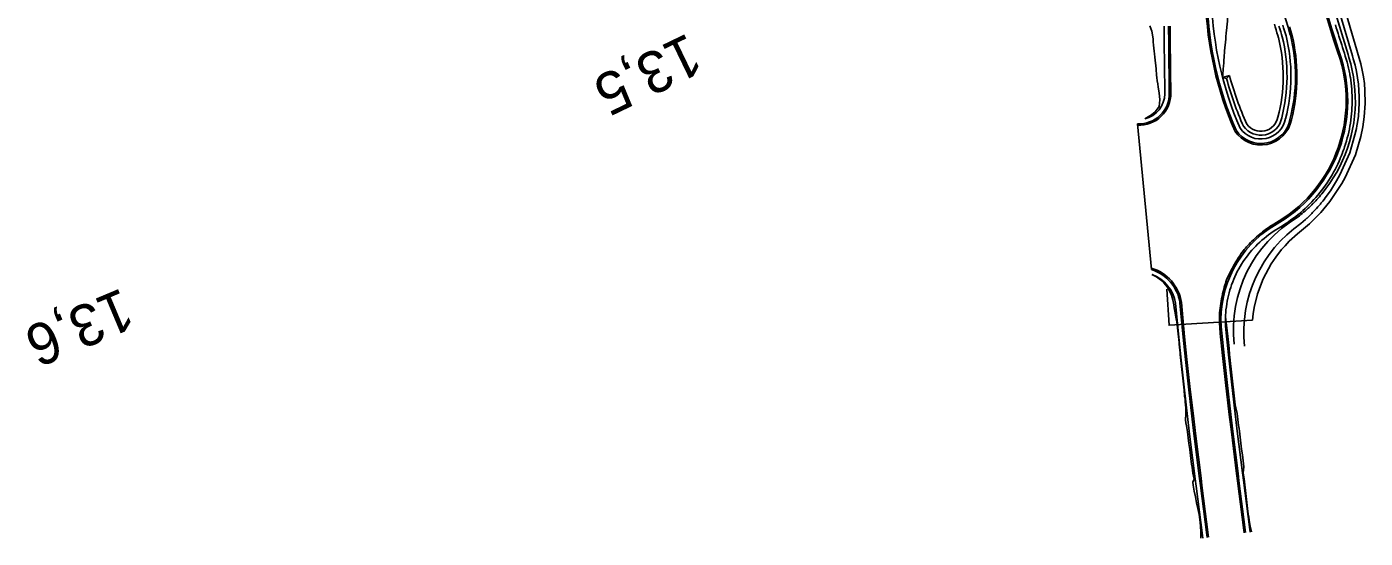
# Model space of a CAD drawing. Extents: x -723225 to -722352, y -1040354 to -1039760.
# Drawn here: x -722813.7 to -722589.4, y -1040267.5 to -1040181.7 of the extents above; entities that cross this region are included whole.
import ezdxf

# ---------------------------------------------------------------- set-up
doc = ezdxf.new("R2010")
doc.units = 0
for name, color, linetype in [('SO 03_01_01', 7, 'Continuous'), ('SO 05_30_01', 7, 'Continuous'), ('SO 05_30_02', 7, 'Continuous'), ('SO 05_73_06', 7, 'Continuous')]:
    doc.layers.add(name, color=color, linetype=linetype)

msp = doc.modelspace()

# ---------------------------------------------------------------- linework, layer by layer
at = {"layer": 'SO 05_30_01'}
msp.add_line((-722625.21, -1040222.47), (-722627.56, -1040198.01), dxfattribs=at)
for points in [[(-722613.29, -1040190.21), (-722613.26, -1040189.78), (-722613.19, -1040188.77), (-722613.16, -1040188.36), (-722613.11, -1040187.77), (-722613.08, -1040187.36), (-722613.03, -1040186.78), (-722612.95, -1040185.86), (-722612.95, -1040185.78), (-722612.86, -1040184.78), (-722612.83, -1040184.36), (-722612.77, -1040183.77), (-722612.73, -1040183.36), (-722612.68, -1040182.78), (-722612.6, -1040181.86), (-722612.59, -1040181.77), (-722612.49, -1040180.77), (-722612.45, -1040180.36), (-722612.38, -1040179.89), (-722612.29, -1040179.56), (-722612.17, -1040179.07), (-722612.02, -1040178.37)], [(-722626.35, -1040197.16), (-722625.2, -1040196.52), (-722624.58, -1040196.01), (-722623.94, -1040195.12), (-722623.82, -1040193.96), (-722623.9, -1040192.82), (-722624.07, -1040191.85), (-722624.16, -1040191.3), (-722624.26, -1040190.82), (-722624.32, -1040190.24), (-722624.36, -1040189.82), (-722624.45, -1040188.82), (-722624.51, -1040188.24), (-722624.55, -1040187.82), (-722624.65, -1040186.82), (-722624.7, -1040186.24), (-722624.75, -1040185.82), (-722624.85, -1040184.82), (-722624.91, -1040184.24), (-722624.95, -1040183.82), (-722625, -1040183.39), (-722625.18, -1040182.49), (-722625.33, -1040182.03), (-722625.5, -1040181.58)], [(-722622.97, -1040192.95), (-722622.97, -1040192.79), (-722622.98, -1040192.47), (-722622.98, -1040192.15), (-722622.98, -1040191.83), (-722622.99, -1040191.51), (-722622.99, -1040191.19), (-722623, -1040190.87), (-722623, -1040190.55), (-722623.01, -1040190.24), (-722623.01, -1040189.92), (-722623.02, -1040189.6), (-722623.02, -1040189.28), (-722623.02, -1040188.96), (-722623.02, -1040188.94), (-722623.03, -1040188.64), (-722623.03, -1040188.32), (-722623.03, -1040188), (-722623.04, -1040187.68), (-722623.04, -1040187.37), (-722623.04, -1040187.35), (-722623.05, -1040187.05), (-722623.05, -1040186.73), (-722623.05, -1040186.41), (-722623.06, -1040186.09), (-722623.06, -1040185.77), (-722623.06, -1040185.46), (-722623.07, -1040185.14), (-722623.07, -1040184.82), (-722623.07, -1040184.5), (-722623.07, -1040184.18), (-722623.08, -1040183.86), (-722623.08, -1040183.55), (-722623.08, -1040183.23), (-722623.09, -1040182.91), (-722623.09, -1040182.59), (-722623.09, -1040182.27), (-722623.09, -1040181.95), (-722623.1, -1040181.64)], [(-722622.22, -1040192.84), (-722622.22, -1040192.78), (-722622.23, -1040192.46), (-722622.23, -1040192.14), (-722622.23, -1040191.82), (-722622.24, -1040191.5), (-722622.24, -1040191.18), (-722622.25, -1040190.86), (-722622.25, -1040190.54), (-722622.26, -1040190.23), (-722622.26, -1040189.91), (-722622.27, -1040189.59), (-722622.27, -1040189.27), (-722622.27, -1040188.95), (-722622.27, -1040188.93), (-722622.28, -1040188.63), (-722622.28, -1040188.31), (-722622.29, -1040187.99), (-722622.29, -1040187.68), (-722622.29, -1040187.36), (-722622.29, -1040187.34), (-722622.3, -1040187.04), (-722622.3, -1040186.72), (-722622.3, -1040186.4), (-722622.31, -1040186.08), (-722622.31, -1040185.77), (-722622.31, -1040185.45), (-722622.32, -1040185.13), (-722622.32, -1040184.81), (-722622.32, -1040184.49), (-722622.32, -1040184.17), (-722622.33, -1040183.86), (-722622.33, -1040183.54), (-722622.33, -1040183.22), (-722622.34, -1040182.9), (-722622.34, -1040182.58), (-722622.34, -1040182.27), (-722622.34, -1040181.95), (-722622.35, -1040181.63)], [(-722621.97, -1040192.84), (-722621.97, -1040192.77), (-722621.98, -1040192.45), (-722621.98, -1040192.13), (-722621.98, -1040191.82), (-722621.99, -1040191.5), (-722621.99, -1040191.18), (-722622, -1040190.86), (-722622, -1040190.54), (-722622.01, -1040190.22), (-722622.01, -1040189.9), (-722622.02, -1040189.58), (-722622.02, -1040189.27), (-722622.02, -1040188.95), (-722622.02, -1040188.92), (-722622.03, -1040188.63), (-722622.03, -1040188.31), (-722622.04, -1040187.99), (-722622.04, -1040187.67), (-722622.04, -1040187.36), (-722622.04, -1040187.34), (-722622.05, -1040187.04), (-722622.05, -1040186.72), (-722622.05, -1040186.4), (-722622.06, -1040186.08), (-722622.06, -1040185.76), (-722622.06, -1040185.45), (-722622.07, -1040185.13), (-722622.07, -1040184.81), (-722622.07, -1040184.49), (-722622.07, -1040184.17), (-722622.08, -1040183.85), (-722622.08, -1040183.54), (-722622.08, -1040183.22), (-722622.09, -1040182.9), (-722622.09, -1040182.58), (-722622.09, -1040182.26), (-722622.09, -1040181.95), (-722622.1, -1040181.63)], [(-722616.94, -1040267.53), (-722616.95, -1040266.52), (-722616.97, -1040265.52), (-722617.1, -1040264.39), (-722617.23, -1040263.53), (-722617.44, -1040262.55), (-722617.65, -1040261.57), (-722617.65, -1040261.57), (-722617.86, -1040260.59), (-722618.06, -1040259.61), (-722618.2, -1040258.61), (-722618.27, -1040258.12), (-722618.03, -1040257.59), (-722618.28, -1040256.61), (-722618.42, -1040255.62), (-722618.49, -1040255.12), (-722618.56, -1040254.63), (-722618.69, -1040253.64), (-722618.81, -1040252.64), (-722618.81, -1040252.64), (-722618.94, -1040251.65), (-722619.06, -1040250.66), (-722619.12, -1040250.16), (-722619.18, -1040249.67), (-722619.36, -1040248.68), (-722619.47, -1040248.18), (-722619.52, -1040247.69), (-722619.48, -1040246.68), (-722619.45, -1040246.17), (-722619.43, -1040245.67), (-722619.54, -1040244.67), (-722619.59, -1040244.17), (-722619.65, -1040243.68), (-722619.75, -1040242.68), (-722619.81, -1040242.18), (-722619.86, -1040241.69), (-722619.97, -1040240.7), (-722620.02, -1040240.19), (-722620.07, -1040239.7), (-722620.18, -1040238.71), (-722620.18, -1040238.69), (-722620.28, -1040237.71), (-722620.33, -1040237.2), (-722620.38, -1040236.72), (-722620.48, -1040235.72), (-722620.49, -1040235.7), (-722620.58, -1040234.73), (-722620.64, -1040234.21), (-722620.68, -1040233.73), (-722620.78, -1040232.74), (-722620.78, -1040232.71), (-722620.88, -1040231.74), (-722620.98, -1040231.22), (-722621.08, -1040230.75), (-722621.23, -1040229.76), (-722621.24, -1040229.74), (-722621.4, -1040228.85), (-722621.47, -1040228.35)], [(-722616.62, -1040267.5), (-722616.68, -1040267.07), (-722617.74, -1040258.8), (-722617.89, -1040257.57), (-722618.77, -1040250.51), (-722619.12, -1040247.62), (-722619.75, -1040242.2), (-722620.25, -1040237.63), (-722620.64, -1040233.86), (-722621.19, -1040228.1)], [(-722615.88, -1040267.4), (-722615.94, -1040266.97), (-722617, -1040258.7), (-722617.15, -1040257.48), (-722618.03, -1040250.42), (-722618.38, -1040247.53), (-722619, -1040242.11), (-722619.5, -1040237.55), (-722619.89, -1040233.79), (-722620.44, -1040228.01)], [(-722615.63, -1040267.37), (-722615.69, -1040266.94), (-722616.75, -1040258.67), (-722616.9, -1040257.45), (-722617.78, -1040250.39), (-722618.13, -1040247.5), (-722618.76, -1040242.08), (-722619.26, -1040237.53), (-722619.65, -1040233.76), (-722620.2, -1040227.98)], [(-722609.68, -1040266.61), (-722609.74, -1040266.18), (-722610.8, -1040257.91), (-722610.95, -1040256.69), (-722611.82, -1040249.66), (-722612.17, -1040246.79), (-722612.79, -1040241.41), (-722613.29, -1040236.89), (-722613.68, -1040233.16), (-722613.78, -1040232.1)], [(-722609.43, -1040266.57), (-722609.49, -1040266.14), (-722610.55, -1040257.88), (-722610.7, -1040256.66), (-722611.58, -1040249.63), (-722611.92, -1040246.76), (-722612.54, -1040241.38), (-722613.04, -1040236.86), (-722613.43, -1040233.14), (-722613.53, -1040232.09)], [(-722608.47, -1040266.46), (-722608.65, -1040265.48), (-722608.86, -1040264.5), (-722608.92, -1040264), (-722608.98, -1040263.5), (-722609.1, -1040262.51), (-722609.22, -1040261.52), (-722609.22, -1040261.52), (-722609.34, -1040260.52), (-722609.46, -1040259.53), (-722609.58, -1040258.54), (-722609.7, -1040257.55), (-722609.82, -1040256.55), (-722609.82, -1040256.55), (-722609.75, -1040255.54), (-722609.86, -1040254.54), (-722609.86, -1040254.54), (-722609.98, -1040253.55), (-722610.1, -1040252.56), (-722610.1, -1040252.56), (-722610.23, -1040251.57), (-722610.29, -1040251.07), (-722610.35, -1040250.57), (-722610.47, -1040249.58), (-722610.53, -1040249.09), (-722610.6, -1040248.59), (-722610.72, -1040247.6), (-722610.78, -1040247.11), (-722610.84, -1040246.6), (-722611.08, -1040245.63), (-722611.18, -1040245.14), (-722611.23, -1040244.64), (-722611.35, -1040243.64), (-722611.4, -1040243.16), (-722611.46, -1040242.65), (-722611.57, -1040241.66), (-722611.62, -1040241.17), (-722611.68, -1040240.66), (-722611.78, -1040239.68), (-722611.79, -1040239.67), (-722611.89, -1040238.67), (-722611.95, -1040238.19), (-722612, -1040237.68), (-722612.11, -1040236.7), (-722612.11, -1040236.69), (-722612.21, -1040235.69), (-722612.26, -1040235.21), (-722612.32, -1040234.7), (-722612.42, -1040233.7), (-722612.52, -1040232.73), (-722612.52, -1040232.71), (-722612.8, -1040230.38)], [(-722608.69, -1040266.48), (-722608.74, -1040266.05), (-722609.8, -1040257.79), (-722609.96, -1040256.57), (-722610.83, -1040249.54), (-722611.18, -1040246.67), (-722611.8, -1040241.3), (-722612.3, -1040236.78), (-722612.68, -1040233.06), (-722612.79, -1040231.87)]]:
    msp.add_lwpolyline(points, dxfattribs=at)
for centre, radius, start, end in [((-722627.32, -1040192.92), 5.1, 267.2895, 0.8852), ((-722627.32, -1040192.92), 5.35, 267.6754, 0.8852), ((-722627.32, -1040192.92), 4.35, 282.8795, 359.5116), ((-722627.31, -1040229.1), 7.21, 8.9645, 73.2104), ((-722627.31, -1040229.1), 6.96, 9.0345, 72.357), ((-722627.56, -1040228.91), 6.11, 5.2223, 66.5396), ((-722627.31, -1040229.1), 6.21, 9.244, 69.198)]:
    msp.add_arc(centre, radius, start, end, dxfattribs=at)
at = {"layer": 'SO 05_30_02'}
for p, q in [((-722602.08, -1040181.72), (-722601.69, -1040183)), ((-722612.14, -1040189.89), (-722613.29, -1040190.21)), ((-722613.29, -1040190.21), (-722612.62, -1040190.41)), ((-722612.62, -1040190.41), (-722612.14, -1040189.89))]:
    msp.add_line(p, q, dxfattribs=at)
for points in [[(-722600.81, -1040213.73), (-722600.42, -1040213.43), (-722600.18, -1040213.24), (-722599.94, -1040213.04), (-722599.76, -1040212.88), (-722599.71, -1040212.84), (-722599.47, -1040212.64), (-722599.24, -1040212.44), (-722599.01, -1040212.23), (-722598.93, -1040212.15), (-722598.78, -1040212.02), (-722598.56, -1040211.81), (-722598.34, -1040211.59), (-722598.14, -1040211.39), (-722598.12, -1040211.37), (-722597.91, -1040211.15), (-722597.69, -1040210.93), (-722597.48, -1040210.7), (-722597.38, -1040210.59), (-722597.28, -1040210.47), (-722597.07, -1040210.24), (-722596.87, -1040210), (-722596.67, -1040209.77), (-722596.66, -1040209.75), (-722596.44, -1040209.48), (-722595.98, -1040208.88), (-722595.33, -1040207.99), (-722594.73, -1040207.07), (-722594.17, -1040206.12), (-722593.66, -1040205.14), (-722593.18, -1040204.15), (-722592.75, -1040203.13), (-722592.37, -1040202.09), (-722592.04, -1040201.04), (-722591.75, -1040199.98), (-722591.51, -1040198.9), (-722591.42, -1040198.39), (-722591.32, -1040197.82), (-722591.18, -1040196.72), (-722591.08, -1040195.63), (-722591.04, -1040194.52), (-722591.05, -1040193.42), (-722591.1, -1040192.32), (-722591.21, -1040191.22), (-722591.36, -1040190.13), (-722591.56, -1040189.05), (-722591.81, -1040187.97), (-722592.11, -1040186.91), (-722592.27, -1040186.38), (-722594.33, -1040179.64)], [(-722591.94, -1040202.88), (-722591.11, -1040199.87), (-722590.87, -1040198.82), (-722590.77, -1040198.33), (-722590.68, -1040197.77), (-722590.53, -1040196.7), (-722590.43, -1040195.63), (-722590.38, -1040194.55), (-722590.38, -1040193.48), (-722590.43, -1040192.4), (-722590.52, -1040191.33), (-722590.67, -1040190.27), (-722590.86, -1040189.21), (-722591.09, -1040188.16), (-722591.38, -1040187.12), (-722591.54, -1040186.58), (-722593.55, -1040179.84)], [(-722594.38, -1040181.42), (-722594.23, -1040181.89), (-722594.08, -1040182.37), (-722593.93, -1040182.85), (-722593.78, -1040183.32), (-722593.63, -1040183.8), (-722593.48, -1040184.28), (-722593.32, -1040184.75), (-722593.17, -1040185.23), (-722593.02, -1040185.7), (-722592.87, -1040186.18), (-722592.72, -1040186.66), (-722592.72, -1040186.66), (-722592.57, -1040187.14), (-722592.56, -1040187.17), (-722592.43, -1040187.65), (-722592.3, -1040188.13), (-722592.29, -1040188.16), (-722592.18, -1040188.65), (-722592.18, -1040188.65), (-722592.07, -1040189.14), (-722592.07, -1040189.16), (-722591.97, -1040189.65), (-722591.97, -1040189.67), (-722591.89, -1040190.16), (-722591.88, -1040190.18), (-722591.81, -1040190.67), (-722591.81, -1040190.69), (-722591.75, -1040191.19), (-722591.69, -1040191.69), (-722591.69, -1040191.71), (-722591.65, -1040192.21), (-722591.64, -1040192.22), (-722591.61, -1040192.72), (-722591.61, -1040192.73), (-722591.59, -1040193.23), (-722591.59, -1040193.25), (-722591.57, -1040193.75), (-722591.57, -1040193.77), (-722591.57, -1040194.27), (-722591.57, -1040194.28), (-722591.58, -1040194.78), (-722591.58, -1040194.81), (-722591.61, -1040195.31), (-722591.61, -1040195.33), (-722591.65, -1040195.83), (-722591.7, -1040196.33), (-722591.74, -1040196.83), (-722591.78, -1040197.33), (-722591.79, -1040197.38), (-722591.87, -1040197.88), (-722591.87, -1040197.88), (-722591.96, -1040198.38), (-722592.04, -1040198.87), (-722592.04, -1040198.89), (-722592.15, -1040199.38), (-722592.15, -1040199.41), (-722592.27, -1040199.9), (-722592.39, -1040200.38), (-722592.51, -1040200.87), (-722592.53, -1040200.92), (-722592.68, -1040201.39), (-722592.68, -1040201.4), (-722592.84, -1040201.87), (-722592.99, -1040202.35), (-722593, -1040202.37), (-722593.17, -1040202.84), (-722593.18, -1040202.87), (-722593.37, -1040203.33), (-722593.56, -1040203.79), (-722593.56, -1040203.8), (-722593.75, -1040204.26), (-722593.77, -1040204.3), (-722593.99, -1040204.75), (-722594.21, -1040205.2), (-722594.21, -1040205.2), (-722594.43, -1040205.65), (-722594.45, -1040205.69), (-722594.7, -1040206.12), (-722594.7, -1040206.13), (-722594.95, -1040206.56), (-722595.2, -1040206.99), (-722595.21, -1040207.01), (-722595.48, -1040207.44), (-722595.5, -1040207.47), (-722595.78, -1040207.88), (-722596.06, -1040208.29), (-722596.34, -1040208.7), (-722596.36, -1040208.73), (-722596.66, -1040209.13), (-722596.67, -1040209.15), (-722596.98, -1040209.54), (-722597.29, -1040209.93), (-722597.32, -1040209.96), (-722597.65, -1040210.34), (-722597.65, -1040210.34), (-722597.98, -1040210.71), (-722598.32, -1040211.09), (-722598.35, -1040211.12), (-722598.7, -1040211.47), (-722598.7, -1040211.47), (-722599.06, -1040211.83), (-722599.41, -1040212.18), (-722599.44, -1040212.21), (-722599.82, -1040212.54), (-722599.82, -1040212.54), (-722600.2, -1040212.87), (-722600.58, -1040213.2), (-722600.61, -1040213.22), (-722601, -1040213.53), (-722601.02, -1040213.54), (-722601.42, -1040213.84), (-722601.83, -1040214.14), (-722602.23, -1040214.43), (-722602.63, -1040214.73), (-722602.67, -1040214.75), (-722603.09, -1040215.02), (-722603.11, -1040215.03), (-722603.53, -1040215.29), (-722603.53, -1040215.29), (-722603.96, -1040215.55), (-722603.96, -1040215.55), (-722604.39, -1040215.81), (-722604.8, -1040216.07), (-722605.19, -1040216.34), (-722605.57, -1040216.62), (-722605.95, -1040216.92), (-722606.34, -1040217.22), (-722606.69, -1040217.52), (-722607.05, -1040217.85), (-722607.42, -1040218.19), (-722607.74, -1040218.51), (-722608.07, -1040218.87), (-722608.41, -1040219.23), (-722608.7, -1040219.58), (-722609, -1040219.96), (-722609.31, -1040220.35), (-722609.56, -1040220.72), (-722609.85, -1040221.13), (-722610.12, -1040221.54), (-722610.34, -1040221.93), (-722610.59, -1040222.36), (-722610.83, -1040222.79), (-722611.02, -1040223.2), (-722611.24, -1040223.65), (-722611.43, -1040224.09), (-722611.6, -1040224.52), (-722611.78, -1040224.99), (-722611.93, -1040225.44), (-722612.07, -1040225.88), (-722612.21, -1040226.36), (-722612.32, -1040226.82), (-722612.42, -1040227.28), (-722612.52, -1040227.77), (-722612.6, -1040228.23), (-722612.66, -1040228.7), (-722612.73, -1040229.19), (-722612.76, -1040229.65), (-722612.78, -1040230.13), (-722612.81, -1040230.63), (-722612.82, -1040231.06), (-722612.8, -1040231.55), (-722612.79, -1040231.87)], [(-722604.61, -1040181.28), (-722604.47, -1040181.76), (-722604.47, -1040181.76), (-722604.32, -1040182.24), (-722604.32, -1040182.24), (-722604.18, -1040182.72), (-722604.18, -1040182.72), (-722604.03, -1040183.2), (-722604.03, -1040183.2), (-722603.92, -1040183.57)], [(-722603.84, -1040181.6), (-722603.69, -1040182.08), (-722603.69, -1040182.08), (-722603.55, -1040182.56), (-722603.55, -1040182.56), (-722603.4, -1040183.04), (-722603.4, -1040183.04), (-722603.29, -1040183.41)], [(-722603.21, -1040181.45), (-722603.06, -1040181.93), (-722603.06, -1040181.93), (-722602.92, -1040182.41), (-722602.92, -1040182.41), (-722602.77, -1040182.89), (-722602.77, -1040182.89), (-722602.66, -1040183.26)], [(-722601.94, -1040183.06), (-722602.32, -1040181.8)], [(-722595.21, -1040209.25), (-722594.2, -1040207.55), (-722593.66, -1040206.54), (-722591.94, -1040202.88)], [(-722600.16, -1040214.74), (-722599.37, -1040214.03), (-722599.18, -1040213.86), (-722599.13, -1040213.81), (-722598.9, -1040213.59), (-722598.66, -1040213.37), (-722598.43, -1040213.14), (-722598.35, -1040213.05), (-722598.2, -1040212.9), (-722597.98, -1040212.67), (-722597.76, -1040212.43), (-722597.56, -1040212.21), (-722597.54, -1040212.19), (-722597.33, -1040211.95), (-722597.11, -1040211.71), (-722596.9, -1040211.46), (-722596.8, -1040211.34), (-722596.7, -1040211.21), (-722596.49, -1040210.96), (-722596.29, -1040210.71), (-722596.1, -1040210.45), (-722596.09, -1040210.43), (-722595.21, -1040209.25)]]:
    msp.add_lwpolyline(points, dxfattribs=at)
for centre, radius, start, end in [((-722288.01, -1040085.73), 321.99, 193.3888, 198.3654), ((-722288.01, -1040085.73), 321.74, 193.3888, 198.3654), ((-722363.17, -1040108.95), 250, 192.1239, 196.941), ((-722557, -1040175.62), 59.16, 181.8353, 203.4879), ((-722557, -1040175.62), 58.91, 181.8353, 203.4879), ((-722557, -1040175.62), 58.16, 181.8353, 203.4198), ((-722630.02, -1040190.04), 29.19, 345.5198, 13.968), ((-722630.09, -1040190.05), 26.96, 345.2976, 13.9491), ((-722630.07, -1040190.05), 27.58, 345.371, 13.9556), ((-722630.07, -1040190.05), 28.24, 345.4086, 13.955), ((-722630.02, -1040190.04), 28.94, 345.5198, 13.968), ((-722616.34, -1040194.1), 23.77, 299.2745, 16.9229), ((-722616.34, -1040194.1), 24.02, 299.2745, 16.9229), ((-722559.52, -1040176.19), 54.97, 194.9954, 203.8481), ((-722562.14, -1040176.77), 51.69, 194.7024, 204.3371), ((-722606.88, -1040196.34), 5.22, 213.6328, 349.1747), ((-722606.88, -1040196.34), 4.97, 213.6328, 349.1747), ((-722606.88, -1040196.34), 4.22, 214.5023, 349.1747), ((-722606.88, -1040196.34), 3.57, 215.3808, 349.1747), ((-722606.88, -1040196.34), 2.92, 216.4055, 349.1747)]:
    msp.add_arc(centre, radius, start, end, dxfattribs=at)
for centre, major_axis, ratio, start_param, end_param in [((-722589.15, -1040232.59), (-22.01, 3.75), 0.987501, 5.428977, 6.561327), ((-722595.42, -1040230.53), (12.51, 13.42), 0.979538, 1.290512, 2.396659), ((-722587.45, -1040233.07), (-6.12, -21.45), 0.999855, 4.02567, 5.091259)]:
    msp.add_ellipse(centre, major_axis=major_axis, ratio=ratio, start_param=start_param, end_param=end_param, dxfattribs=at)
msp.add_open_spline([(-722604.72, -1040214.83), (-722605.72, -1040215.44), (-722606.67, -1040216.15), (-722609.03, -1040218.26), (-722610.3, -1040219.82), (-722612.29, -1040223.26), (-722613.01, -1040225.14), (-722613.76, -1040228.73), (-722613.89, -1040230.43), (-722613.78, -1040232.1)], degree=3, dxfattribs=at)
at = {"layer": 'SO 05_73_06'}
msp.add_lwpolyline([(-722592.59, -1040179.56), (-722590.12, -1040187.92), (-722589.88, -1040189.01), (-722589.68, -1040190.11), (-722589.53, -1040191.22), (-722589.45, -1040192.42), (-722589.38, -1040194.58), (-722589.54, -1040196.81), (-722589.79, -1040198.51), (-722590.14, -1040200.12), (-722591, -1040203.23), (-722592.77, -1040206.99), (-722593.33, -1040208.04), (-722595.29, -1040211.03), (-722596.81, -1040212.88), (-722598.7, -1040214.78), (-722600.76, -1040216.47), (-722602.12, -1040217.71), (-722602.83, -1040218.45), (-722603.4, -1040219.11), (-722604.37, -1040220.35), (-722605.14, -1040221.5), (-722606.48, -1040224), (-722607.44, -1040226.53), (-722608.01, -1040228.82), (-722608.19, -1040229.88), (-722608.28, -1040230.93), (-722622.26, -1040231.81), (-722622.63, -1040225.77)], dxfattribs=at)

# ---------------------------------------------------------------- texts
at = {"layer": 'SO 03_01_01'}
for s, rotation, p in [('13,5', 205.8028, (-722702.88, -1040182.7)), ('13,6', 202.7911, (-722797.78, -1040225.47))]:
    msp.add_text(s, height=7, rotation=rotation, dxfattribs=at).set_placement(p)

doc.saveas('drawing.dxf')
